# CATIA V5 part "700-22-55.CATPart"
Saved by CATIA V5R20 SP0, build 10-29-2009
Part number: 700-22-55
Revision: ANY
Definition: UNKNOWN
Nomenclature: 700-22-55
Source: Unknown
Bounding box of the stored display mesh (mm): x -11 to 11, y 0 to 55, z -11 to 11
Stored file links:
  C:\Users\Utente\Desktop\IO LAVORO\3D X SITO CF\X SITO\700\700-22-55.CATPart
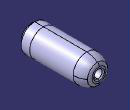
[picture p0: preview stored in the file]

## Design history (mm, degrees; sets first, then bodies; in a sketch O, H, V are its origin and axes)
Body1 "Rivoluzione1" (main body)
  Solid1: solid without history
